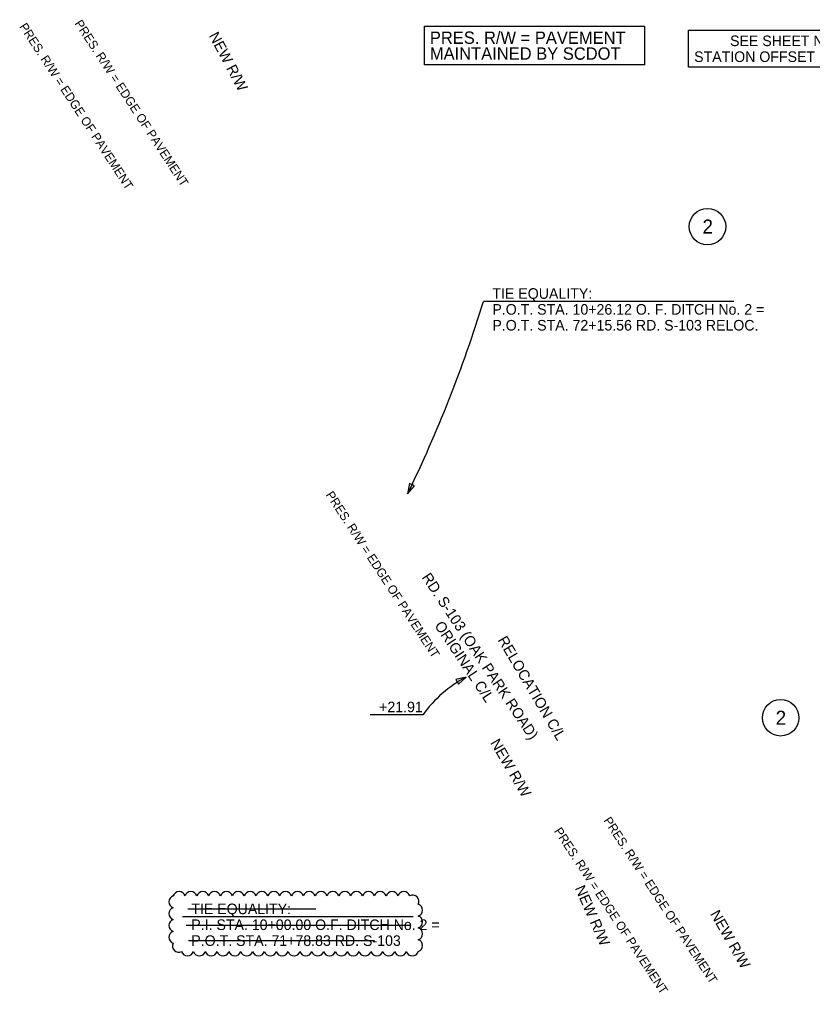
# Model space of a CAD drawing. Extents: x 1964377 to 1966966, y 1116414 to 1123213.
# Drawn here: x 1966177 to 1966627, y 1122661 to 1123213 of the extents above; entities that cross this region are included whole.
import ezdxf

# ---------------------------------------------------------------- set-up
doc = ezdxf.new("R2010")
doc.units = 0
for name, color, linetype in [('RD_EX_DV_TX_Prop', 7, 'Continuous'), ('RD_EX_RW_TX', 7, 'Continuous'), ('RD_HC_Data', 7, 'Continuous'), ('RD_HC_Data_Rel', 7, 'Continuous'), ('RD_PD_RW_TX', 7, 'Continuous'), ('RD_TX_RoadID', 7, 'Continuous'), ('RD_TX_StaOff', 7, 'Continuous')]:
    doc.layers.add(name, color=color, linetype=linetype)

msp = doc.modelspace()

# ---------------------------------------------------------------- linework, layer by layer
at = {"layer": 'RD_EX_DV_TX_Prop'}
for centre in [(1966567.67, 1123095.2), (1966609.17, 1122816.46)]:
    msp.add_circle(centre, 10.35, dxfattribs=at)
at = {"layer": 'RD_EX_RW_TX'}
msp.add_lwpolyline([(1966407.17, 1123208.92), (1966531.87, 1123208.92), (1966531.87, 1123186.92), (1966407.17, 1123186.92)], close=True, dxfattribs=at)
at = {"layer": 'RD_HC_Data'}
for p, q in [((1966582.52, 1123052.73), (1966440.63, 1123052.73)), ((1966272.85, 1122708.01), (1966345.54, 1122708.01)), ((1966400.7, 1122703.51), (1966269.83, 1122703.51)), ((1966271.84, 1122698.75), (1966399.05, 1122698.75)), ((1966273.19, 1122689.99), (1966378.69, 1122689.99))]:
    msp.add_line(p, q, dxfattribs=at)
msp.add_lwpolyline([(1966398.69, 1122949.44), (1966397.57, 1122943.55), (1966401.49, 1122948.09)], close=True, dxfattribs=at)
for centre, radius, start, end in [((1965686.87, 1123286.92), 789.3, 334.21225, 342.73976), ((1966265.61, 1122712.01), 3.52, 107.5, 252.5), ((1966267.91, 1122714.31), 3.52, 17.5, 162.5), ((1966274.62, 1122714.31), 3.52, 17.5, 162.5), ((1966281.34, 1122714.31), 3.52, 17.5, 162.5), ((1966288.05, 1122714.31), 3.52, 17.5, 162.5), ((1966294.76, 1122714.31), 3.52, 17.5, 162.5), ((1966301.47, 1122714.31), 3.52, 17.5, 162.5), ((1966308.19, 1122714.31), 3.52, 17.5, 162.5), ((1966314.9, 1122714.31), 3.52, 17.5, 162.5), ((1966321.61, 1122714.31), 3.52, 17.5, 162.5), ((1966328.32, 1122714.31), 3.52, 17.5, 162.5), ((1966335.04, 1122714.31), 3.52, 17.5, 162.5), ((1966341.75, 1122714.31), 3.52, 17.5, 162.5), ((1966348.46, 1122714.31), 3.52, 17.5, 162.5), ((1966355.18, 1122714.31), 3.52, 17.5, 162.5), ((1966361.89, 1122714.31), 3.52, 17.5, 162.5), ((1966368.6, 1122714.31), 3.52, 17.5, 162.5), ((1966375.31, 1122714.31), 3.52, 17.5, 162.5), ((1966382.03, 1122714.31), 3.52, 17.5, 162.5), ((1966388.74, 1122714.31), 3.52, 17.5, 162.5), ((1966395.45, 1122714.31), 3.52, 17.5, 162.5), ((1966400.45, 1122712.25), 3.52, 332.8074, 117.8074), ((1966265.61, 1122705.3), 3.52, 107.5, 252.5), ((1966402.52, 1122707.29), 3.52, 287.5, 72.5), ((1966265.61, 1122698.58), 3.52, 107.5, 252.5), ((1966402.52, 1122700.58), 3.52, 287.5, 72.5), ((1966402.52, 1122693.86), 3.52, 287.5, 72.5), ((1966265.61, 1122691.87), 3.52, 107.5, 252.5), ((1966267.68, 1122686.91), 3.52, 152.8074, 297.8074), ((1966402.52, 1122687.15), 3.52, 287.5, 72.5), ((1966272.68, 1122684.85), 3.52, 197.5, 342.5), ((1966279.39, 1122684.85), 3.52, 197.5, 342.5), ((1966286.11, 1122684.85), 3.52, 197.5, 342.5), ((1966292.82, 1122684.85), 3.52, 197.5, 342.5), ((1966299.53, 1122684.85), 3.52, 197.5, 342.5), ((1966306.24, 1122684.85), 3.52, 197.5, 342.5), ((1966312.96, 1122684.85), 3.52, 197.5, 342.5), ((1966319.67, 1122684.85), 3.52, 197.5, 342.5), ((1966326.38, 1122684.85), 3.52, 197.5, 342.5), ((1966333.1, 1122684.85), 3.52, 197.5, 342.5), ((1966339.81, 1122684.85), 3.52, 197.5, 342.5), ((1966346.52, 1122684.85), 3.52, 197.5, 342.5), ((1966353.23, 1122684.85), 3.52, 197.5, 342.5), ((1966359.95, 1122684.85), 3.52, 197.5, 342.5), ((1966366.66, 1122684.85), 3.52, 197.5, 342.5), ((1966373.37, 1122684.85), 3.52, 197.5, 342.5), ((1966380.08, 1122684.85), 3.52, 197.5, 342.5), ((1966386.8, 1122684.85), 3.52, 197.5, 342.5), ((1966393.51, 1122684.85), 3.52, 197.5, 342.5), ((1966400.22, 1122684.85), 3.52, 197.5, 342.5)]:
    msp.add_arc(centre, radius, start, end, dxfattribs=at)
at = {"layer": 'RD_PD_RW_TX'}
msp.add_line((1966406.23, 1122818.12), (1966376.38, 1122818.12), dxfattribs=at)
msp.add_lwpolyline([(1966426.32, 1122835.49), (1966430.7, 1122839.59), (1966424.86, 1122838.23)], close=True, dxfattribs=at)
msp.add_arc((1966464.47, 1122776.44), 71.61, 118.1346, 144.4067, dxfattribs=at)
at = {"layer": 'RD_TX_StaOff'}
msp.add_lwpolyline([(1966556.98, 1123206.64), (1966698.53, 1123206.64), (1966698.53, 1123185.64), (1966556.98, 1123185.64)], close=True, dxfattribs=at)

# ---------------------------------------------------------------- texts
at = {"layer": 'RD_EX_DV_TX_Prop'}
for p in [(1966564.83, 1123091.21), (1966606.33, 1122812.47)]:
    msp.add_text('2', height=8, dxfattribs=at).set_placement(p)
at = {"layer": 'RD_EX_RW_TX'}
for p in [(1966177.05, 1123208.68), (1966208.4, 1123210.48), (1966350.9, 1122942.98), (1966508.46, 1122758.16), (1966480.43, 1122752.18)]:
    msp.add_text('PRES. R/W = EDGE OF PAVEMENT', height=5, rotation=303.2086, dxfattribs=at).set_placement(p)
for s, p in [('PRES. R/W = PAVEMENT ', (1966410.17, 1123198.92)), ('MAINTAINED BY SCDOT', (1966410.17, 1123189.92))]:
    msp.add_text(s, height=7, dxfattribs=at).set_placement(p)
at = {"layer": 'RD_HC_Data'}
for s, p in [('TIE EQUALITY:', (1966445.63, 1123054.23)), ('P.O.T. STA. 10+26.12 O. F. DITCH No. 2 =', (1966445.63, 1123045.23)), ('P.O.T. STA. 72+15.56 RD. S-103 RELOC.', (1966445.63, 1123036.23)), ('TIE EQUALITY:', (1966274.83, 1122705.01)), ('P.I. STA. 10+00.00 O.F. DITCH No. 2 =', (1966274.83, 1122696.01)), ('P.O.T. STA. 71+78.83 RD. S-103', (1966274.83, 1122687.01))]:
    msp.add_text(s, height=6, dxfattribs=at).set_placement(p)
at = {"layer": 'RD_HC_Data_Rel'}
msp.add_text('RELOCATION C/L', height=6, rotation=300.5889, dxfattribs=at).set_placement((1966448.46, 1122860.62))
at = {"layer": 'RD_PD_RW_TX'}
for rotation, p in [(298.0718, (1966284.62, 1123203.62)), (300.432, (1966444.22, 1122802.27)), (293.6499, (1966492.35, 1122719.79)), (299.6231, (1966569, 1122705.19))]:
    msp.add_text('NEW R/W', height=6, rotation=rotation, dxfattribs=at).set_placement(p)
msp.add_text('+21.91', height=6, dxfattribs=at).set_placement((1966381.38, 1122819.62))
at = {"layer": 'RD_TX_RoadID'}
for s, p in [('RD. S-103 (OAK PARK ROAD)', (1966405.32, 1122896.16)), ('ORIGINAL C/L', (1966412.56, 1122868.8))]:
    msp.add_text(s, height=6, rotation=303.6494, dxfattribs=at).set_placement(p)
at = {"layer": 'RD_TX_StaOff'}
for s, p in [('SEE SHEET NO. 5B FOR', (1966580.48, 1123197.64)), ('STATION OFFSET INFORMATION', (1966560.07, 1123188.64))]:
    msp.add_text(s, height=6, dxfattribs=at).set_placement(p)

doc.saveas('drawing.dxf')
